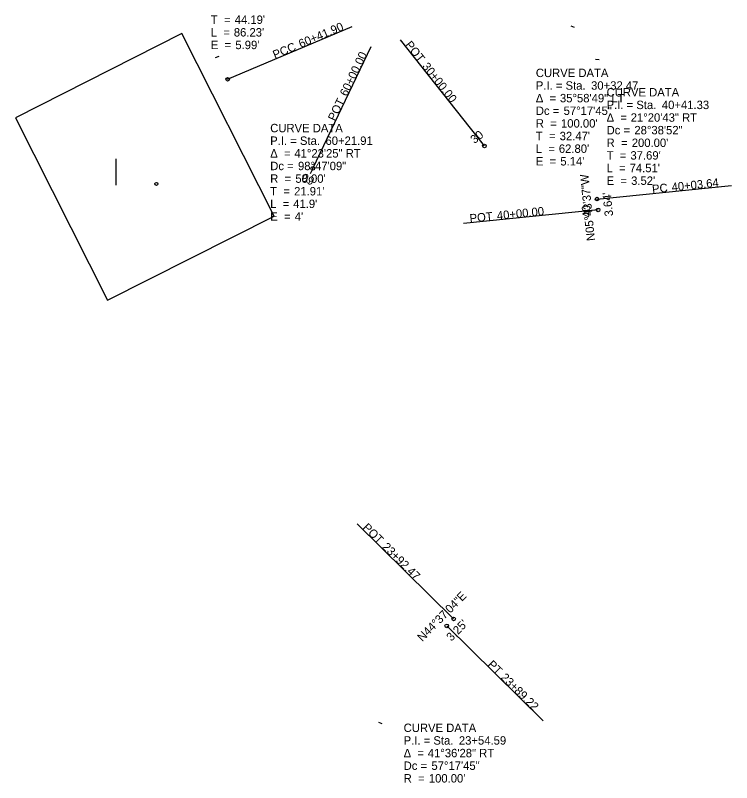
# Model space of a CAD drawing. Extents: x 1564698 to 1565044, y 636021 to 637179.
# Drawn here: x 1564697.9 to 1564936, y 636351.1 to 636606.3 of the extents above; entities that cross this region are included whole.
import ezdxf

# ---------------------------------------------------------------- set-up
doc = ezdxf.new("R2010")
doc.units = 0
for name, color, linetype in [('_CIVIL_CONSTRUCTION', 7, 'Continuous'), ('GE_P_Alignment_1000_Curve_Data', 7, 'Continuous'), ('GE_P_Alignment_1000_Stations', 7, 'Continuous'), ('GE_P_Alignment_100_Curve_Data', 7, 'Continuous'), ('GE_P_Alignment_100_Distances', 7, 'Continuous'), ('GE_P_Alignment_100_Stations', 7, 'Continuous'), ('GE_P_Alignment_500_Curve_Data', 7, 'Continuous'), ('GE_P_Alignment_500_Stations', 7, 'Continuous'), ('SH_Named_Boundary', 7, 'Continuous')]:
    doc.layers.add(name, color=color, linetype=linetype)

msp = doc.modelspace()

# ---------------------------------------------------------------- linework, layer by layer
at = {"layer": '_CIVIL_CONSTRUCTION'}
msp.add_circle((1564744.75, 636550.24), 0.5, dxfattribs=at)
msp.add_circle((1564744.75, 636550.24), 0.5, dxfattribs=at)
at = {"layer": 'GE_P_Alignment_1000_Stations'}
for p, q in [((1564768.46, 636585.03), (1564809.89, 636602.6)), ((1564853.84, 636562.85), (1564825.88, 636598.11)), ((1564796.77, 636555.38), (1564816.23, 636595.95)), ((1564853.84, 636562.85), (1564852.59, 636564.42)), ((1564796.77, 636555.38), (1564795.9, 636553.58)), ((1564891.27, 636545.22), (1564936.04, 636549.71)), ((1564891.63, 636541.59), (1564846.86, 636537.1)), ((1564891.63, 636541.59), (1564889.64, 636541.39)), ((1564843.61, 636405.57), (1564811.58, 636437.17)), ((1564841.33, 636403.25), (1564873.36, 636371.65))]:
    msp.add_line(p, q, dxfattribs=at)
for centre in [(1564768.46, 636585.03), (1564853.84, 636562.85), (1564796.77, 636555.38), (1564891.27, 636545.22), (1564891.63, 636541.59), (1564843.61, 636405.57), (1564841.33, 636403.25)]:
    msp.add_circle(centre, 0.6, dxfattribs=at)
at = {"layer": 'GE_P_Alignment_100_Distances'}
msp.add_line((1564731.24, 636558.62), (1564731.24, 636549.8), dxfattribs=at)
at = {"layer": 'GE_P_Alignment_100_Stations'}
for p, q in [((1564768.46, 636585.03), (1564809.89, 636602.6)), ((1564883.8, 636602.22), (1564882.7, 636602.69)), ((1564853.84, 636562.85), (1564825.88, 636598.11)), ((1564796.77, 636555.38), (1564816.23, 636595.95)), ((1564765.49, 636592.57), (1564764.36, 636592.15)), ((1564892.01, 636591.46), (1564890.82, 636591.62)), ((1564853.84, 636562.85), (1564852.59, 636564.42)), ((1564796.77, 636555.38), (1564795.9, 636553.58)), ((1564891.27, 636545.22), (1564936.04, 636549.71)), ((1564891.63, 636541.59), (1564846.86, 636537.1)), ((1564891.63, 636541.59), (1564889.64, 636541.39)), ((1564843.61, 636405.57), (1564811.58, 636437.17)), ((1564841.33, 636403.25), (1564873.36, 636371.65)), ((1564819.88, 636370.71), (1564818.77, 636371.17))]:
    msp.add_line(p, q, dxfattribs=at)
for centre in [(1564768.46, 636585.03), (1564853.84, 636562.85), (1564796.77, 636555.38), (1564891.27, 636545.22), (1564891.63, 636541.59), (1564843.61, 636405.57), (1564841.33, 636403.25)]:
    msp.add_circle(centre, 0.6, dxfattribs=at)
at = {"layer": 'GE_P_Alignment_500_Stations'}
for p, q in [((1564768.46, 636585.03), (1564809.89, 636602.6)), ((1564853.84, 636562.85), (1564825.88, 636598.11)), ((1564796.77, 636555.38), (1564816.23, 636595.95)), ((1564853.84, 636562.85), (1564852.59, 636564.42)), ((1564796.77, 636555.38), (1564795.9, 636553.58)), ((1564891.27, 636545.22), (1564936.04, 636549.71)), ((1564891.63, 636541.59), (1564846.86, 636537.1)), ((1564891.63, 636541.59), (1564889.64, 636541.39)), ((1564843.61, 636405.57), (1564811.58, 636437.17)), ((1564841.33, 636403.25), (1564873.36, 636371.65))]:
    msp.add_line(p, q, dxfattribs=at)
for centre in [(1564768.46, 636585.03), (1564853.84, 636562.85), (1564796.77, 636555.38), (1564891.27, 636545.22), (1564891.63, 636541.59), (1564843.61, 636405.57), (1564841.33, 636403.25)]:
    msp.add_circle(centre, 0.6, dxfattribs=at)
at = {"layer": 'SH_Named_Boundary'}
msp.add_lwpolyline([(1564783.88, 636539.54), (1564753.24, 636600.21), (1564697.87, 636572.25), (1564728.51, 636511.57)], close=True, dxfattribs=at)

# ---------------------------------------------------------------- texts
at = {"layer": 'GE_P_Alignment_1000_Curve_Data'}
for s, p in [('T  = ', (1564762.87, 636603.46)), ("44.19'", (1564770.8, 636603.46)), ('L  = ', (1564762.87, 636599.26)), ("86.23'", (1564770.51, 636599.26)), ('E  = ', (1564762.87, 636595.06)), ("5.99'", (1564771.02, 636595.06)), ('CURVE DATA', (1564870.93, 636585.77)), ('P.I. = Sta. ', (1564870.93, 636581.57)), ('30+32.47', (1564889.3, 636581.57)), ('CURVE DATA', (1564894.46, 636579.32)), ('Δ  = ', (1564870.93, 636577.37)), ('35°58\'49" LT', (1564878.95, 636577.37)), ('Dc = ', (1564870.93, 636573.17)), ('57°17\'45"', (1564880.17, 636573.17)), ('P.I. = Sta. ', (1564894.46, 636575.12)), ('40+41.33', (1564912.83, 636575.12)), ('Δ  = ', (1564894.46, 636570.92)), ('21°20\'43" RT', (1564902.48, 636570.92)), ('R  = ', (1564870.93, 636568.97)), ("100.00'", (1564879.3, 636568.97)), ('CURVE DATA', (1564782.61, 636567.41)), ('Dc = ', (1564894.46, 636566.72)), ('28°38\'52"', (1564903.7, 636566.72)), ('P.I. = Sta. ', (1564782.61, 636563.21)), ('60+21.91', (1564800.98, 636563.21)), ('T  = ', (1564870.93, 636564.77)), ("32.47'", (1564878.86, 636564.77)), ('L  = ', (1564870.93, 636560.57)), ("62.80'", (1564878.58, 636560.57)), ('R  = ', (1564894.46, 636562.52)), ("200.00'", (1564902.83, 636562.52)), ('Δ  = ', (1564782.61, 636559.01)), ('41°23\'25" RT', (1564790.64, 636559.01)), ('T  = ', (1564894.46, 636558.32)), ("37.69'", (1564902.39, 636558.32)), ('E  = ', (1564870.93, 636556.37)), ("5.14'", (1564879.08, 636556.37)), ('Dc = ', (1564782.61, 636554.81)), ('98°47\'09"', (1564791.85, 636554.81)), ('L  = ', (1564894.46, 636554.12)), ("74.51'", (1564902.11, 636554.12)), ('R  = ', (1564782.61, 636550.61)), ("58.00'", (1564790.98, 636550.61)), ('E  = ', (1564894.46, 636549.92)), ("3.52'", (1564902.61, 636549.92)), ('T  = ', (1564782.61, 636546.41)), ("21.91'", (1564790.55, 636546.41)), ("41.9'", (1564790.26, 636542.21)), ('L  = ', (1564782.61, 636542.21)), ('E  = ', (1564782.61, 636538.01)), ("4'", (1564790.77, 636538.01)), ('CURVE DATA', (1564826.98, 636367.96)), ('P.I. = Sta. ', (1564826.98, 636363.76)), ('23+54.59', (1564845.35, 636363.76)), ('Δ  = ', (1564826.98, 636359.56)), ('41°36\'28" RT', (1564835.01, 636359.56)), ('Dc = ', (1564826.98, 636355.36)), ('57°17\'45"', (1564836.22, 636355.36)), ('R  = ', (1564826.98, 636351.16)), ("100.00'", (1564835.35, 636351.16))]:
    msp.add_text(s, height=2.8, dxfattribs=at).set_placement(p)
for s, rotation, p in [('N05°43\'37"W', 95.727, (1564890.64, 636531.4)), ("3.64'", 95.727, (1564896.66, 636539.59)), ('N44°37\'04"E', 45.3822, (1564833.19, 636397.86)), ("3.25'", 45.3822, (1564842.86, 636397.97))]:
    msp.add_text(s, height=2.8, rotation=rotation, dxfattribs=at).set_placement(p)
at = {"layer": 'GE_P_Alignment_1000_Stations'}
for s, rotation, p in [('60+41.90', 22.9822, (1564792.79, 636595.4)), ('PCC', 22.9822, (1564784.18, 636591.75)), ('POT', 308.4016, (1564827.29, 636596.41)), ('60+00.00', 64.3724, (1564808.12, 636579.15)), ('30+00.00', 308.4016, (1564832.96, 636589.26)), ('POT', 64.3724, (1564804.17, 636570.92)), ('30', 38.4016, (1564850.54, 636563.48)), ('60', 154.3724, (1564797.64, 636552.14)), ('PC', 5.727, (1564909.72, 636547.11)), ('40+03.64', 5.727, (1564916.21, 636547.77)), ('40+00.00', 5.727, (1564858.13, 636538.28)), ('40', 95.727, (1564889.32, 636539.16)), ('POT', 5.727, (1564849.05, 636537.37)), ('POT', 315.3822, (1564813.14, 636435.7)), ('23+92.47', 315.3822, (1564819.64, 636429.28)), ('PT', 315.3822, (1564854.69, 636390.13)), ('23+89.22', 315.3822, (1564859.03, 636385.85))]:
    msp.add_text(s, height=2.8, rotation=rotation, dxfattribs=at).set_placement(p)
at = {"layer": 'GE_P_Alignment_100_Curve_Data'}
for s, p in [('T  = ', (1564762.87, 636603.46)), ("44.19'", (1564770.8, 636603.46)), ('L  = ', (1564762.87, 636599.26)), ("86.23'", (1564770.51, 636599.26)), ('E  = ', (1564762.87, 636595.06)), ("5.99'", (1564771.02, 636595.06)), ('CURVE DATA', (1564870.93, 636585.77)), ('P.I. = Sta. ', (1564870.93, 636581.57)), ('30+32.47', (1564889.3, 636581.57)), ('CURVE DATA', (1564894.46, 636579.32)), ('Δ  = ', (1564870.93, 636577.37)), ('35°58\'49" LT', (1564878.95, 636577.37)), ('Dc = ', (1564870.93, 636573.17)), ('57°17\'45"', (1564880.17, 636573.17)), ('P.I. = Sta. ', (1564894.46, 636575.12)), ('40+41.33', (1564912.83, 636575.12)), ('Δ  = ', (1564894.46, 636570.92)), ('21°20\'43" RT', (1564902.48, 636570.92)), ('R  = ', (1564870.93, 636568.97)), ("100.00'", (1564879.3, 636568.97)), ('CURVE DATA', (1564782.61, 636567.41)), ('Dc = ', (1564894.46, 636566.72)), ('28°38\'52"', (1564903.7, 636566.72)), ('P.I. = Sta. ', (1564782.61, 636563.21)), ('60+21.91', (1564800.98, 636563.21)), ('T  = ', (1564870.93, 636564.77)), ("32.47'", (1564878.86, 636564.77)), ('L  = ', (1564870.93, 636560.57)), ("62.80'", (1564878.58, 636560.57)), ('R  = ', (1564894.46, 636562.52)), ("200.00'", (1564902.83, 636562.52)), ('Δ  = ', (1564782.61, 636559.01)), ('41°23\'25" RT', (1564790.64, 636559.01)), ('T  = ', (1564894.46, 636558.32)), ("37.69'", (1564902.39, 636558.32)), ('E  = ', (1564870.93, 636556.37)), ("5.14'", (1564879.08, 636556.37)), ('Dc = ', (1564782.61, 636554.81)), ('98°47\'09"', (1564791.85, 636554.81)), ('L  = ', (1564894.46, 636554.12)), ("74.51'", (1564902.11, 636554.12)), ('R  = ', (1564782.61, 636550.61)), ("58.00'", (1564790.98, 636550.61)), ('E  = ', (1564894.46, 636549.92)), ("3.52'", (1564902.61, 636549.92)), ('T  = ', (1564782.61, 636546.41)), ("21.91'", (1564790.55, 636546.41)), ("41.9'", (1564790.26, 636542.21)), ('L  = ', (1564782.61, 636542.21)), ('E  = ', (1564782.61, 636538.01)), ("4'", (1564790.77, 636538.01)), ('CURVE DATA', (1564826.98, 636367.96)), ('P.I. = Sta. ', (1564826.98, 636363.76)), ('23+54.59', (1564845.35, 636363.76)), ('Δ  = ', (1564826.98, 636359.56)), ('41°36\'28" RT', (1564835.01, 636359.56)), ('Dc = ', (1564826.98, 636355.36)), ('57°17\'45"', (1564836.22, 636355.36)), ('R  = ', (1564826.98, 636351.16)), ("100.00'", (1564835.35, 636351.16))]:
    msp.add_text(s, height=2.8, dxfattribs=at).set_placement(p)
for s, rotation, p in [('N05°43\'37"W', 95.727, (1564890.64, 636531.4)), ("3.64'", 95.727, (1564896.66, 636539.59)), ('N44°37\'04"E', 45.3822, (1564833.19, 636397.86)), ("3.25'", 45.3822, (1564842.86, 636397.97))]:
    msp.add_text(s, height=2.8, rotation=rotation, dxfattribs=at).set_placement(p)
at = {"layer": 'GE_P_Alignment_100_Stations'}
for s, rotation, p in [('60+41.90', 22.9822, (1564792.79, 636595.4)), ('PCC', 22.9822, (1564784.18, 636591.75)), ('POT', 308.4016, (1564827.29, 636596.41)), ('60+00.00', 64.3724, (1564808.12, 636579.15)), ('30+00.00', 308.4016, (1564832.96, 636589.26)), ('POT', 64.3724, (1564804.17, 636570.92)), ('30', 38.4016, (1564850.54, 636563.48)), ('60', 154.3724, (1564797.64, 636552.14)), ('PC', 5.727, (1564909.72, 636547.11)), ('40+03.64', 5.727, (1564916.21, 636547.77)), ('40+00.00', 5.727, (1564858.13, 636538.28)), ('40', 95.727, (1564889.32, 636539.16)), ('POT', 5.727, (1564849.05, 636537.37)), ('POT', 315.3822, (1564813.14, 636435.7)), ('23+92.47', 315.3822, (1564819.64, 636429.28)), ('PT', 315.3822, (1564854.69, 636390.13)), ('23+89.22', 315.3822, (1564859.03, 636385.85))]:
    msp.add_text(s, height=2.8, rotation=rotation, dxfattribs=at).set_placement(p)
at = {"layer": 'GE_P_Alignment_500_Curve_Data'}
for s, p in [('T  = ', (1564762.87, 636603.46)), ("44.19'", (1564770.8, 636603.46)), ('L  = ', (1564762.87, 636599.26)), ("86.23'", (1564770.51, 636599.26)), ('E  = ', (1564762.87, 636595.06)), ("5.99'", (1564771.02, 636595.06)), ('CURVE DATA', (1564870.93, 636585.77)), ('P.I. = Sta. ', (1564870.93, 636581.57)), ('30+32.47', (1564889.3, 636581.57)), ('CURVE DATA', (1564894.46, 636579.32)), ('Δ  = ', (1564870.93, 636577.37)), ('35°58\'49" LT', (1564878.95, 636577.37)), ('Dc = ', (1564870.93, 636573.17)), ('57°17\'45"', (1564880.17, 636573.17)), ('P.I. = Sta. ', (1564894.46, 636575.12)), ('40+41.33', (1564912.83, 636575.12)), ('Δ  = ', (1564894.46, 636570.92)), ('21°20\'43" RT', (1564902.48, 636570.92)), ('R  = ', (1564870.93, 636568.97)), ("100.00'", (1564879.3, 636568.97)), ('CURVE DATA', (1564782.61, 636567.41)), ('Dc = ', (1564894.46, 636566.72)), ('28°38\'52"', (1564903.7, 636566.72)), ('P.I. = Sta. ', (1564782.61, 636563.21)), ('60+21.91', (1564800.98, 636563.21)), ('T  = ', (1564870.93, 636564.77)), ("32.47'", (1564878.86, 636564.77)), ('L  = ', (1564870.93, 636560.57)), ("62.80'", (1564878.58, 636560.57)), ('R  = ', (1564894.46, 636562.52)), ("200.00'", (1564902.83, 636562.52)), ('Δ  = ', (1564782.61, 636559.01)), ('41°23\'25" RT', (1564790.64, 636559.01)), ('T  = ', (1564894.46, 636558.32)), ("37.69'", (1564902.39, 636558.32)), ('E  = ', (1564870.93, 636556.37)), ("5.14'", (1564879.08, 636556.37)), ('Dc = ', (1564782.61, 636554.81)), ('98°47\'09"', (1564791.85, 636554.81)), ('L  = ', (1564894.46, 636554.12)), ("74.51'", (1564902.11, 636554.12)), ('R  = ', (1564782.61, 636550.61)), ("58.00'", (1564790.98, 636550.61)), ('E  = ', (1564894.46, 636549.92)), ("3.52'", (1564902.61, 636549.92)), ('T  = ', (1564782.61, 636546.41)), ("21.91'", (1564790.55, 636546.41)), ("41.9'", (1564790.26, 636542.21)), ('L  = ', (1564782.61, 636542.21)), ('E  = ', (1564782.61, 636538.01)), ("4'", (1564790.77, 636538.01)), ('CURVE DATA', (1564826.98, 636367.96)), ('P.I. = Sta. ', (1564826.98, 636363.76)), ('23+54.59', (1564845.35, 636363.76)), ('Δ  = ', (1564826.98, 636359.56)), ('41°36\'28" RT', (1564835.01, 636359.56)), ('Dc = ', (1564826.98, 636355.36)), ('57°17\'45"', (1564836.22, 636355.36)), ('R  = ', (1564826.98, 636351.16)), ("100.00'", (1564835.35, 636351.16))]:
    msp.add_text(s, height=2.8, dxfattribs=at).set_placement(p)
for s, rotation, p in [('N05°43\'37"W', 95.727, (1564890.64, 636531.4)), ("3.64'", 95.727, (1564896.66, 636539.59)), ('N44°37\'04"E', 45.3822, (1564833.19, 636397.86)), ("3.25'", 45.3822, (1564842.86, 636397.97))]:
    msp.add_text(s, height=2.8, rotation=rotation, dxfattribs=at).set_placement(p)
at = {"layer": 'GE_P_Alignment_500_Stations'}
for s, rotation, p in [('60+41.90', 22.9822, (1564792.79, 636595.4)), ('PCC', 22.9822, (1564784.18, 636591.75)), ('POT', 308.4016, (1564827.29, 636596.41)), ('60+00.00', 64.3724, (1564808.12, 636579.15)), ('30+00.00', 308.4016, (1564832.96, 636589.26)), ('POT', 64.3724, (1564804.17, 636570.92)), ('30', 38.4016, (1564850.54, 636563.48)), ('60', 154.3724, (1564797.64, 636552.14)), ('PC', 5.727, (1564909.72, 636547.11)), ('40+03.64', 5.727, (1564916.21, 636547.77)), ('40+00.00', 5.727, (1564858.13, 636538.28)), ('40', 95.727, (1564889.32, 636539.16)), ('POT', 5.727, (1564849.05, 636537.37)), ('POT', 315.3822, (1564813.14, 636435.7)), ('23+92.47', 315.3822, (1564819.64, 636429.28)), ('PT', 315.3822, (1564854.69, 636390.13)), ('23+89.22', 315.3822, (1564859.03, 636385.85))]:
    msp.add_text(s, height=2.8, rotation=rotation, dxfattribs=at).set_placement(p)

doc.saveas('drawing.dxf')
